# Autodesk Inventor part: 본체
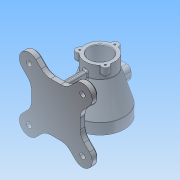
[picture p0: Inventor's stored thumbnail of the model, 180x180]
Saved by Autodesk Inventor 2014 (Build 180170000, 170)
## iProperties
Created: 2018-03
Part Number: 본체
Material: 알루미늄 6061
Document SubType Name: Modeling
Designer: net
Density: 2.71 g/cm^3
Appearance: 알루미늄 - 평지
Mass: 1014.31 g
Surface Area: 854.69 cm^2
Volume: 374.284 cm^3
Author: net
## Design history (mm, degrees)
sketch "스케치1"
  geometry: C1 r 45 at (0, 0); 1 further point
  constraints: 1 centre point, 1 coincident
  dimensions: "d0" = 90 diameter of C1
extrude "돌출1" new body sketch "스케치1" distance "d1" = 20; taper "d2" = 0 deg
node "작업 평면2"
sketch "스케치2"
  geometry: C1 r 27.5 at (0, 0); 1 further point
  constraints: 1 centre point, 1 coincident
  dimensions: "d4" = 55 diameter of C1
extrude "돌출2" join sketch "스케치2" distance "d5" = 23; taper "d6" = 0 deg
sketch "스케치3"
  geometry: L1 (-27.5, 77)-(27.5, 77) reference; L2 (-27.5, 100)-(27.5, 100) reference; L3 (45, 20)-(-45, 20) reference; L4 (-45, 0)-(45, 0) reference; L5 (27.5, 77)-(45, 20); L6 (-27.5, 77)-(-45, 20); L7 (0, 77)-(0, 20); L8 (27.5, 77)-(0, 77); L9 (45, 20)-(0, 20); L10 (27.5, 100)-(27.5, 77) reference; L11 (45, 0)-(45, 20) reference; 1 further point
  constraints: 10 end point, 2 collinear, 2 midpoint
revolve "회전1" sketch "스케치3" stored, may be unused: angle "d7" = 90 deg
sketch "스케치4"
  geometry: C1 r 27.5 at (0, 0) reference; C2 r 20 at (0, 0)
  constraints: 1 centre point, 1 coincident
  dimensions: "d8" = 40 diameter of C2
extrude "돌출3" cut sketch "스케치4" distance "d9" = 30; taper "d10" = 0 deg
sketch "스케치5"
  geometry: C1 r 20 at (0, 0) reference; C2 r 26 at (0, 0)
  constraints: 1 centre point, 1 coincident
  dimensions: "d11" = 52 diameter of C2
extrude "돌출4" cut sketch "스케치5" distance "d12" = 47; taper "d13" = 0 deg
sketch "스케치6"
  geometry: C1 r 45 at (0, 0) reference; C2 r 35 at (0, 0)
  constraints: 1 centre point, 1 coincident
  dimensions: "d14" = 70 diameter of C2
extrude "돌출5" cut sketch "스케치6" distance "d15" = 23; taper "d16" = 0 deg
sketch "스케치7"
  geometry: 1 further point
node "작업 평면3"
fillet "모깎기1" dims "d18" = 3
sketch "스케치8"
  geometry: C1 r 20 at (0, 0) reference; C2 r 7 at (0, 27.5); C3 r 7 at (-23.816, -13.75); C4 r 7 at (23.816, -13.75); 1 further point
  constraints: 3 centre point, 1 vertical alignment, 8 other
  dimensions: "d19" = 14 diameter of C2; "d22" = 360 deg dimension on C1.centre C2.centre (derived)
extrude "돌출6" join sketch "스케치8" distance "d24" = 15; taper "d25" = 0 deg
fillet "모깎기2" dims "d26" = 3
fillet "모깎기3" dims "d27" = 1
sketch "스케치9"
  geometry: A1 r 7 centre (0, 27.5) between (6.999, 27.373) and (-6.999, 27.373) reference; A2 r 7 centre (-23.816, -13.75) between (-27.205, -7.625) and (-20.206, -19.748) reference; A3 r 7 centre (23.816, -13.75) between (20.206, -19.748) and (27.205, -7.625) reference
hole "구멍1" sketch "스케치9" at (-23.816, -13.75), (0, 27.5), (23.816, -13.75) diameter "d28" = 3.242; stored, may be unused: countersink angle "d32" = 90 deg, drill point angle "d34" = 118 deg; dims "d29" = 9, "d30" = 4, "d31" = 2, "d33" = 11
sketch "스케치10"
  geometry: L1 (0, 0)-(0, 40); L2 (0, 0)-(-34.641, 20); L3 (0, 0)-(-34.641, -20); L4 (0, 0)-(0, -40); L5 (0, 0)-(34.641, -20); L6 (0, 0)-(34.641, 20); C1 r 35 at (0, 0) reference; C2 r 45 at (0, 0) reference
  constraints: 12 end point, 1 vertical, 19 other
  dimensions: "d35" = 40 distance of L1.start L1.end; "d38" = 360 deg dimension on C1.centre L1.end (derived)
hole "구멍2" sketch "스케치10" at (0, 40), (-34.641, 20), (-34.641, -20), (0, -40), (34.641, 20), (34.641, -20) diameter "d40" = 3.242; stored, may be unused: countersink angle "d44" = 90 deg, drill point angle "d46" = 118 deg; dims "d41" = 9, "d42" = 4, "d43" = 2, "d45" = 11
node "작업 평면4"
sketch "스케치14"
  geometry: L1 (-44.988, 69.554)-(-62.214, 86.78) reference; L2 (-44.988, 50.01)-(-44.988, 69.554) reference; L3 (-44.988, 69.554)-(-44.988, 30.466) reference; L4 (-44.988, 30.466)-(-62.214, 13.241) reference; L5 (0.012, 5.01)-(-19.532, 5.01) reference; L6 (-36.758, -12.215)-(-19.532, 5.01) reference; L7 (0.012, 5.01)-(19.556, 5.01) reference; L8 (36.781, -12.215)-(19.556, 5.01) reference; L9 (45.012, 30.466)-(62.237, 13.241) reference; L10 (45.012, 50.01)-(45.012, 30.466) reference; L11 (45.012, 50.01)-(45.012, 69.554) reference; L12 (45.012, 69.554)-(62.237, 86.78) reference; L13 (36.781, 112.236)-(19.556, 95.01) reference; L14 (0.012, 95.01)-(19.556, 95.01) reference; L15 (0.012, 95.01)-(-19.532, 95.01) reference; L16 (-36.758, 112.236)-(-19.532, 95.01) reference; A1 r 18 centre (-49.486, 99.508) between (-62.214, 86.78) and (-36.758, 112.236) reference; A2 r 18 centre (-49.486, 0.513) between (-62.214, 13.241) and (-36.758, -12.215) reference; A3 r 18 centre (49.509, 0.513) between (36.781, -12.215) and (62.237, 13.241) reference; A4 r 18 centre (49.509, 99.508) between (62.237, 86.78) and (36.781, 112.236) reference; 1 further point
extrude "돌출7" join sketch "스케치14" distance "d87" = 12; taper "d88" = 0 deg
sketch "스케치15"
  geometry: L1 (-62.237, -13.241)-(-45.012, -30.466) reference; L2 (-45.012, -30.466)-(-45.012, -69.554) reference; L3 (-45.012, -69.554)-(-62.237, -86.78) reference; L4 (-36.781, -112.236)-(-19.556, -95.01) reference; L5 (-19.556, -95.01)-(19.532, -95.01) reference; L6 (19.532, -95.01)-(36.758, -112.236) reference; L7 (62.214, -86.78)-(44.988, -69.554) reference; L8 (44.988, -69.554)-(44.988, -30.466) reference; L9 (44.988, -30.466)-(62.214, -13.241) reference; L10 (36.758, 12.215)-(19.532, -5.01) reference; L11 (19.532, -5.01)-(-19.556, -5.01) reference; L12 (-19.556, -5.01)-(-36.781, 12.215) reference; A1 r 18 centre (-49.509, -0.513) between (-36.781, 12.215) and (-62.237, -13.241) reference; A2 r 18 centre (-49.509, -99.508) between (-62.237, -86.78) and (-36.781, -112.236) reference; A3 r 18 centre (49.486, -99.508) between (36.758, -112.236) and (62.214, -86.78) reference; A4 r 18 centre (49.486, -0.513) between (62.214, -13.241) and (36.758, 12.215) reference; 1 further point
sketch "스케치16"
  geometry: L1 (-45.012, -30.466)-(-45.012, -69.554) reference; L2 (19.532, -5.01)-(-19.556, -5.01) reference; L3 (-45.012, -50.01)-(-0.012, -50.01); L4 (-0.012, -50.01)-(-0.012, -13.01); L5 (-0.012, -50.01)-(-0.012, -87.01); L6 (-0.012, -13.01)-(-4.012, -13.01); L7 (-4.012, -13.01)-(-4.012, -87.01); L8 (-4.012, -87.01)-(-0.012, -87.01); L9 (-0.012, -13.01)-(3.988, -13.01); L10 (3.988, -13.01)-(3.988, -87.01); L11 (3.988, -87.01)-(-0.012, -87.01); 1 further point
  constraints: 18 end point, 4 parallel, 3 perpendicular, 1 collinear, 1 midpoint
  dimensions: "d89" = 45 distance of L3.start L3.end; "d90" = 37 distance of L3.end L4.end; "d91" = 37 distance of L3.end L5.end; "d92" = 4 distance of L4.end L6.end; "d93" = 4 distance of L4.end L9.end
extrude "돌출8" join sketch "스케치16" stored distance "d94" = 12; taper "d95" = 0 deg
sketch "스케치17"
  geometry: 1 further point
node "작업 평면5"
sketch "스케치18"
  geometry: L1 (-4.012, -70)-(-4.012, -27.206) reference; L2 (3.988, -70)-(-4.012, -70) reference; L3 (3.988, -70)-(3.988, -27.209) reference; L4 (19.532, -70)-(-19.556, -70) reference; L5 (-0.012, -70)-(-24.012, -70); L6 (-24.012, -70)-(-19.879, -22.769); L7 (-24.012, -70)-(23.4, -70); L8 (-19.879, -22.769)-(-4.012, -30.433); L9 (-4.012, -70)-(-4.012, -30.433); L10 (-4.012, -70)-(-24.012, -70); A1 r 27.5 centre (0, 0) between (-4.012, -27.206) and (3.988, -27.209) reference; 1 further point
  constraints: 12 end point, 2 point on line, 1 collinear, 1 equal length, 1 horizontal, 1 midpoint, 1 perpendicular
  dimensions: "d97" = 24 distance of L5.start L5.end; "d98" = 85 deg angle of L7 L6
extrude "돌출9" join sketch "스케치18" stored distance "d99" = 8; taper "d100" = 0 deg
fillet "모깎기4" dims "d101" = 25
chamfer "모따기1" distance "d102" = 3; stored, may be unused: second distance "d103" = 2, angle "d104" = 45 deg
sketch "스케치19"
  geometry: C1 r 5 at (49.486, -99.508); C2 r 5 at (49.486, -0.513); C3 r 5 at (-49.509, -0.513); C4 r 5 at (-49.509, -99.508); A1 r 15 centre (49.486, -0.513) between (60.092, -11.119) and (38.879, 10.094) reference; A2 r 15 centre (-49.509, -0.513) between (-38.903, 10.094) and (-60.116, -11.119) reference; A3 r 15 centre (-49.509, -99.508) between (-60.116, -88.901) and (-38.903, -110.114) reference; A4 r 15 centre (49.486, -99.508) between (38.879, -110.114) and (60.092, -88.901) reference; 1 further point
  constraints: 4 centre point, 4 coincident
  dimensions: "d105" = 10 diameter of C1; "d106" = 10 diameter of C2; "d107" = 10 diameter of C3; "d108" = 10 diameter of C4
extrude "돌출10" cut sketch "스케치19" stored distance "d109" = 8; taper "d110" = 0 deg
fillet "모깎기5" dims "d111" = 3
fillet "모깎기6" dims "d112" = 3
fillet "모깎기7" dims "d113" = 3
fillet "모깎기8" dims "d114" = 3
sketch "스케치20"
  geometry: L1 (-33.02, 11)-(-33.02, 0) reference; L2 (-45, 0)-(45, 0) reference; L3 (0, 0)-(0, 50); L4 (12.5, 37.5)-(-12.5, 37.5); L5 (-12.5, 37.5)-(-12.5, 62.5); L6 (-12.5, 62.5)-(12.5, 62.5); L7 (12.5, 62.5)-(12.5, 37.5); L8 (12.5, 37.5)-(-12.5, 62.5); L9 (-12.5, 37.5)-(12.5, 62.5)
  constraints: 14 end point, 2 midpoint, 2 parallel, 2 perpendicular, 1 horizontal
  dimensions: "d115" = 50 distance of L3.start L3.end; "d116" = 25 distance of L5.end L6.end; "d117" = 25 distance of L4.end L5.end
extrude "돌출11" join sketch "스케치20" stored distance "d118" = 8; taper "d119" = 0 deg
sketch "스케치21"
  geometry: L1 (-7.5, -57.5)-(7.5, -57.5); L2 (7.5, -57.5)-(7.5, -42.5); L3 (7.5, -42.5)-(-7.5, -42.5); L4 (-7.5, -42.5)-(-7.5, -57.5); L5 (-7.5, -57.5)-(7.5, -42.5); L6 (7.5, -57.5)-(-7.5, -42.5); 2 further points
  constraints: 12 end point, 2 midpoint, 2 parallel, 1 horizontal, 1 perpendicular
  dimensions: "d120" = 15 distance of L3.end L2.end; "d121" = 15 distance of L2.end L1.end
extrude "돌출12" cut sketch "스케치21" distance "d122" = 40; taper "d123" = 0 deg
fillet "모깎기9" dims "d124" = 8
fillet "모깎기10" dims "d125" = 1
fillet "모깎기11" dims "d126" = 3
chamfer "모따기2" distance "d127" = 1; stored, may be unused: second distance "d128" = 2, angle "d129" = 45 deg
chamfer "모따기3" distance "d130" = 1; stored, may be unused: second distance "d131" = 2, angle "d132" = 45 deg
sketch "스케치22"
  geometry: 1 further point
fillet "모깎기12" dims "d133" = 3
sketch "스케치23"
  geometry: 1 further point
sketch "스케치24"
  geometry: L1 (-31.732, -33.364)-(-31.732, -66.547); L2 (-31.732, -66.547)-(-36.535, -66.547); L3 (-36.535, -66.547)-(-36.535, -33.364); L4 (-36.535, -33.364)-(-31.732, -33.364); 1 further point
  constraints: 2 other
feature "엠보싱1" sketch "스케치24" dims "d134" = 0.5, "d135" = 0
node "솔리드1"
mirror "대칭1"
node "투영된 루프2"
node "투영된 루프6"
other parameters: "d17" = 45, "d47" = -82
